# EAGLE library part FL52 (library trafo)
TRANSFORMER 2 primary winding, 2 secondary windings, mounting holes BLOCK
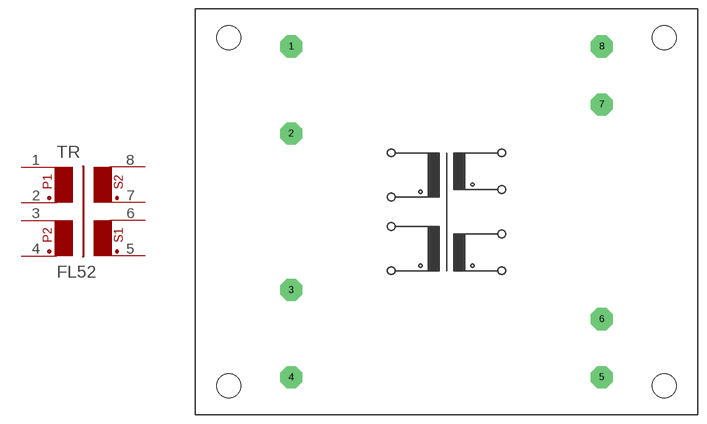
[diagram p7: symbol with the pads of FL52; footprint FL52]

Designator prefix TR

## FL52  [FL52]
1  1  pas
2  2  pas
3  3  pas
4  4  pas
5  5  pas
6  6  pas
7  7  pas
8  8  pas

## Footprint FL52 (pad centres in mm)
TRANSFORMER 2 primary winding, 2 secondary windings, mounting holes
drill 1.397 pad 3.81 octagon: 1 -26.746,28.499; 2 -26.746,13.487; 3 -26.746,-13.487; 4 -26.746,-28.499; 5 26.746,-28.499; 6 26.746,-18.491; 7 26.746,18.491; 8 26.746,28.499
hole 4.115 at -37.49,-29.997
hole 4.115 at -37.49,29.997
hole 4.115 at 37.49,29.997
hole 4.115 at 37.49,-29.997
